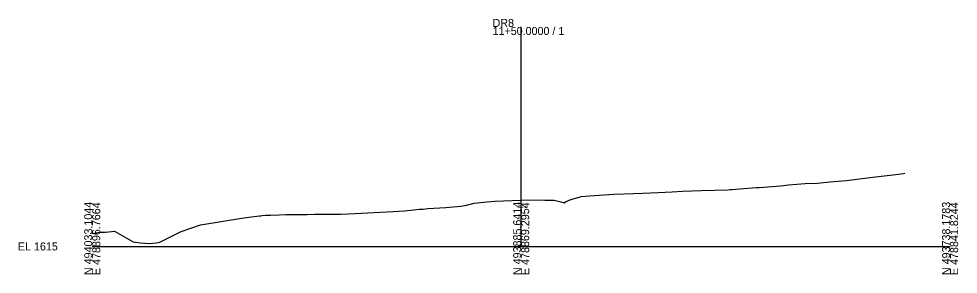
# Model space of a CAD drawing. Extents: x 24 to 353, y -10 to 3552.
# Drawn here: x 24.3 to 352.8, y 1490.3 to 1579.5 of the extents above; entities that cross this region are included whole.
import ezdxf

# ---------------------------------------------------------------- set-up
doc = ezdxf.new("R2010")
doc.units = 0
for name, color, linetype in [('Exist Cross Section Cell', 7, 'Continuous'), ('Exist XS Center Line Elevation Label', 7, 'Continuous'), ('Exist XS Ground Line', 7, 'Continuous'), ('Scratch_Level_5', 7, 'Continuous')]:
    doc.layers.add(name, color=color, linetype=linetype)

msp = doc.modelspace()

# ---------------------------------------------------------------- linework, layer by layer
at = {"layer": 'Exist Cross Section Cell'}
for p, q in [((200, 1500), (200, 1576.68)), ((50, 1500), (200, 1500)), ((200, 1500), (350, 1500))]:
    msp.add_line(p, q, dxfattribs=at)
at = {"layer": 'Exist XS Ground Line'}
msp.add_lwpolyline([(50, 1504.57), (52.65, 1504.95), (54.68, 1505.03), (57.78, 1505.28), (64.34, 1501.6), (66.75, 1501.26), (68.49, 1501.16), (70.02, 1501.07), (72.31, 1501.25), (73.58, 1501.44), (81.15, 1505.18), (87.9, 1507.53), (88.63, 1507.67), (102.2, 1509.85), (104.71, 1510.24), (108.46, 1510.7), (108.92, 1510.74), (109.42, 1510.76), (110.58, 1510.92), (112.38, 1510.98), (115.41, 1511.08), (117.73, 1511.11), (121.09, 1511.13), (122.49, 1511.12), (123.63, 1511.15), (124.2, 1511.19), (125.12, 1511.16), (127.89, 1511.23), (129.44, 1511.26), (131.35, 1511.24), (136.98, 1511.29), (139.67, 1511.41), (141.93, 1511.47), (155.24, 1512.22), (159.19, 1512.47), (162.43, 1512.79), (164.44, 1512.99), (164.82, 1513.03), (165.58, 1513.05), (167.35, 1513.26), (173.63, 1513.63), (178.86, 1514.04), (180.83, 1514.39), (183.53, 1515.11), (188.13, 1515.54), (190.78, 1515.76), (199.78, 1516.17), (207.36, 1516.23), (208.24, 1516.22), (211.48, 1516.2), (213.83, 1515.59), (215.03, 1515.24), (215.51, 1515.62), (217.34, 1516.38), (220.33, 1517.26), (220.97, 1517.45), (223.92, 1517.63), (232.41, 1518.21), (239.32, 1518.46), (242.58, 1518.56), (247.89, 1518.88), (252.75, 1519.09), (256.47, 1519.26), (262.93, 1519.52), (272.34, 1519.82), (273.1, 1519.84), (273.62, 1519.88), (276.42, 1520.09), (282.2, 1520.55), (283.28, 1520.6), (290.78, 1521.15), (293.45, 1521.48), (299.35, 1522.03), (303.62, 1522.12), (307.93, 1522.55), (313.8, 1523.04), (316.5, 1523.43), (323.97, 1524.32), (331.03, 1525.17), (333.66, 1525.52), (334.15, 1525.56)], dxfattribs=at)
at = {"layer": 'Scratch_Level_5'}
msp.add_lwpolyline([(50, 1504.57), (52.65, 1504.95), (54.68, 1505.03), (57.78, 1505.28), (64.34, 1501.6), (66.75, 1501.26), (68.49, 1501.16), (70.02, 1501.07), (72.31, 1501.25), (73.58, 1501.44), (81.15, 1505.18), (87.9, 1507.53), (88.63, 1507.67), (102.2, 1509.85), (104.71, 1510.24), (108.46, 1510.7), (108.92, 1510.74), (109.42, 1510.76), (110.58, 1510.92), (112.38, 1510.98), (115.41, 1511.08), (117.73, 1511.11), (121.09, 1511.13), (122.49, 1511.12), (123.63, 1511.15), (124.2, 1511.19), (125.12, 1511.16), (127.89, 1511.23), (129.44, 1511.26), (131.35, 1511.24), (136.98, 1511.29), (139.67, 1511.41), (141.93, 1511.47), (155.24, 1512.22), (159.19, 1512.47), (162.43, 1512.79), (164.44, 1512.99), (164.82, 1513.03), (165.58, 1513.05), (167.35, 1513.26), (173.63, 1513.63), (178.86, 1514.04), (180.83, 1514.39), (183.53, 1515.11), (188.13, 1515.54), (190.78, 1515.76), (199.78, 1516.17), (207.36, 1516.23), (208.24, 1516.22), (211.48, 1516.2), (213.83, 1515.59), (215.03, 1515.24), (215.51, 1515.62), (217.34, 1516.38), (220.33, 1517.26), (220.97, 1517.45), (223.92, 1517.63), (232.41, 1518.21), (239.32, 1518.46), (242.58, 1518.56), (247.89, 1518.88), (252.75, 1519.09), (256.47, 1519.26), (262.93, 1519.52), (272.34, 1519.82), (273.1, 1519.84), (273.62, 1519.88), (276.42, 1520.09), (282.2, 1520.55), (283.28, 1520.6), (290.78, 1521.15), (293.45, 1521.48), (299.35, 1522.03), (303.62, 1522.12), (307.93, 1522.55), (313.8, 1523.04), (316.5, 1523.43), (323.97, 1524.32), (331.03, 1525.17), (333.66, 1525.52), (334.15, 1525.56)], dxfattribs=at)

# ---------------------------------------------------------------- texts
at = {"layer": 'Exist Cross Section Cell'}
for s, p in [('DR8', (190, 1576.68)), ('11+50.0000 / 1', (190, 1573.88)), ('EL 1615', (24, 1498.6))]:
    msp.add_text(s, height=2.8, dxfattribs=at).set_placement(p)
for s, p in [('N 494033.1044', (50, 1490)), ('E 478896.7664', (52.8, 1490)), ('N 493885.6414', (200, 1490)), ('E 478869.2954', (202.8, 1490)), ('N 493738.1783', (350, 1490)), ('E 478841.8244', (352.8, 1490))]:
    msp.add_text(s, height=2.8, rotation=90, dxfattribs=at).set_placement(p)
at = {"layer": 'Exist XS Center Line Elevation Label'}
msp.add_text('1631.17', height=0.75, dxfattribs=at).set_placement((198.58, 1513.42))

doc.saveas('drawing.dxf')
